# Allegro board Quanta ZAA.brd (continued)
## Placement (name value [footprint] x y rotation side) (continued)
C4736  *for15@10p/50v_4  [C0402]  169.84 81.99 0 bottom
C4737  *for15@10p/50v_4  [C0402]  172.4 82.57 180 bottom
C4748  0.1u/16v_4  [C0402]  28 67.71 0 top
C4749  0.1u/16v_4  [C0402]  19.23 70.66 180 top
C4750  0.1u/16v_4  [C0402]  21.39 68.35 0 bottom
C4751  0.1u/16v_4  [C0402]  21.52 63.9 270 top
C4752  0.1u/16v_4  [C0402]  22.54 63.9 270 top
C4753  4.7u/10v_6  [C0603]  19.36 72.54 270 top
C4754  2.2u/6.3v_6  [C0603]  20.28 63.37 270 top
C4762  typec@0.1u/25v/x5r_4  [C0402]  19.51 121.56 180 bottom
C4763  typec@0.1u/25v/x5r_4  [C0402]  19.51 120.54 180 bottom
C4764  typec@0.1u/25v_4  [C0402]  10.75 117.11 0 top
C4765  typec@10u/6.3v/x5r_6  [C0603]  28.12 109.24 90 top
C4766  typec@10u/6.3v/x5r_6  [C0603]  36.76 109.75 0 top
C4767  typec@0.1u/25v_4  [C0402]  19.49 112.54 90 top
C4768  typec@0.1u/25v_4  [C0402]  10.75 116.12 0 top
C4769  typec@10u/6.3v/x5r_6  [C0603]  36.76 108.48 0 top
C4770  typec@0.1u/25v/x5r_4  [C0402]  19.51 116.76 180 bottom
C4771  typec@0.1u/25v/x5r_4  [C0402]  19.51 117.65 180 bottom
C4772  typec@150u/6.3v_3528  [C3528]  37.65 106.06 180 top
C4773  typec@0.1u/16v_4_x7r  [C0402]  28.84 117.57 180 bottom
C4774  typec@0.1u/16v_4_x7r  [C0402]  32.01 120.62 0 bottom
C4775  *typec@10u/6.3v_6  [C0603]  27.87 114.04 0 top
C4776  typec@0.1u/16v_4_x7r  [C0402]  35.24 120.54 0 top
C4777  typec@0.1u/16v_4_x7r  [C0402]  35.24 119.53 0 top
C4778  typec@0.1u/16v_4_x7r  [C0402]  35.24 122.57 0 top
C4779  typec@0.1u/16v_4_x7r  [C0402]  35.24 121.56 0 top
C4780  typec@0.1u/16v_4_x7r  [C0402]  35.24 117.49 0 top
C4781  typec@0.1u/16v_4_x7r  [C0402]  37.27 116.48 0 top
C4782  *ioac@0.1u/16v_4  [C0402]  48.9 70.38 90 top
C4783  0.1u/16v_4  [C0402]  22.92 52.09 0 top
C4784  0.1u/16v_4_x7r  [C0402]  17.07 43.33 270 top
C4785  0.1u/16v_4_x7r  [C0402]  20.5 55.14 270 top
C4786  0.1u/16v_4_x7r  [C0402]  18.34 55.14 270 top
C4787  0.1u/16v_4_x7r  [C0402]  22.92 53.87 180 top
C4788  ev_a@10u/6.3v_6  [C0603]  223.2 121.43 90 bottom
C4793  *220p/50v_4  [C0402]  193.55 23.95 270 bottom
C4794  *220p/50v_4  [C0402]  192.59 24.07 270 bottom
C4795  *220p/50v_4  [C0402]  190.68 24.12 270 bottom
C4796  *220p/50v_4  [C0402]  191.62 24.12 270 bottom
C4797  *220p/50v_4  [C0402]  177.48 23.9 270 bottom
C4798  *220p/50v_4  [C0402]  176.51 23.9 270 bottom
C4799  *220p/50v_4  [C0402]  175.55 23.9 270 bottom
C4800  *220p/50v_4  [C0402]  174.58 23.9 270 bottom
C4801  *220p/50v_4  [C0402]  181.34 23.9 270 bottom
C4802  *220p/50v_4  [C0402]  180.37 23.9 270 bottom
C4803  *220p/50v_4  [C0402]  179.41 23.9 270 bottom
C4804  *220p/50v_4  [C0402]  178.44 23.9 270 bottom
C4805  *220p/50v_4  [C0402]  185.2 23.9 270 bottom
C4806  *220p/50v_4  [C0402]  184.23 23.9 270 bottom
C4807  *220p/50v_4  [C0402]  183.27 23.9 270 bottom
C4808  *220p/50v_4  [C0402]  182.3 23.9 270 bottom
C4809  *220p/50v_4  [C0402]  197.41 24.07 270 bottom
C4810  *220p/50v_4  [C0402]  196.45 24.07 270 bottom
C4811  *220p/50v_4  [C0402]  195.48 24.07 270 bottom
C4812  *220p/50v_4  [C0402]  194.52 24.07 270 bottom
C4813  *220p/50v_4  [C0402]  189.06 23.9 270 bottom
C4814  *220p/50v_4  [C0402]  188.09 23.9 270 bottom
C4815  *220p/50v_4  [C0402]  186.16 23.9 270 bottom
C4816  *220p/50v_4  [C0402]  187.13 23.9 270 bottom
C4817  typec@100p/50v_4  [C0402]  23.3 114.07 270 top
C4818  typec@1000p/50v_4  [C0402]  22.41 114.07 90 top
C4819  typec@100p/50v_4  [C0402]  16.44 112.54 270 top
C4820  typec@1000p/50v_4  [C0402]  15.42 112.54 90 top
C4821  1000p/50v_4  [C0402]  36.25 64.15 270 top
C4822  *fpd@1000p/50v_4  [C0402]  117.1 34.69 180 top
CN2  *aces_88511-180n  [88511-180N-18P-L]  171.38 93.36 0 top
CN4  sd-card  [SDCARD-PSDAT4-11GLBS1NN4H4-11P]  35.49 19.6 0 top
CN5  50398-04071-001  [GS12401-1011-40P-R-NH-SMT]  121.5 174.4 45 bottom
CN6  bl@kb_backlight  [50591-00401-001-4P-L]  224.2 134.09 270 bottom
CN7  crt conn  [DSUB-95-0005-01-15P]  6.62 79.15 90 bottom
CN8  fan_3p  [HS8803F-3P-L]  57.88 120.4 90 bottom
CN9  c185q2-11311-l  [SATA-C185Q2-11311-L-13P-R]  234.02 101.31 270 bottom
CN10  wlan_ngff conn(type 2230)  [NGFF-NASE0-S6701-TS48-KE-SMT]  196.3 182.75 270 bottom
CN11  rj45  [RJ45-JM361C-HP34AA03-9H-8P]  2.65 104.4 90 bottom
CN12  hdmi connector  [HDMI-10444-19001-19P]  3.35 50.5 90 bottom
CN13  usb3.0 conn  [UB3-YUSB0021-P001A-9P-SMT]  6.82 31.8 90 bottom
CN14  hdd conn  [SATA-C166FQ-12208-L-22P-R]  229.5 44.65 270 bottom
CN16  usb3.0 conn  [UB3-YUSB0021-P001A-9P-SMT]  6.82 15.2 90 bottom
CN17  tp_conn  [50503-0080N-001-8P-L]  122.5 14.95 180 bottom
CN18  spk_conn_4p  [50271-0040N-V01-4P-L]  82.6 12 270 bottom
CN20  for15@kb_conn  [196153-28021-35-28P-L]  164.92 12.65 180 bottom
CN23  ngff_ssd  [NGFF-NASM0-S6701-TS50-KM-SMT]  165.5 98.15 180 bottom
CN95  fpd@conn_aop  [196241-08021-3-8P-L]  110.5 13.45 180 bottom
CN2019  for17@kb_conn  [196153-28021-35-28P-L]  186.46 19.22 180 bottom
CN2020  db_conn  [51619-0260N-001-26P-L]  213.93 16.4 270 bottom
CN2021  typec@usb_type_c  [UB31-DX07B024XJ1AR1000-24P-SMT]  6.6 119.9 90 bottom
D1  1n4148ws  [DSM]  111.18 153.56 90 top
D2  tvs/6pf_4  [C0402]  86.77 87.45 270 bottom
D3  tvs/6pf_4  [C0402]  86.77 85.67 90 bottom
D4  *for17@tvs/6pf_4  [C0402]  133.17 75.2 0 top
D5  *for17@tvs/6pf_4  [C0402]  135.23 75.23 0 top
D6  *az5125-01j  [C0402]  13.65 53.99 90 top
D7  bat54c  [SOT323_213-2_1-1_3-2N7002W]  74.86 50.18 90 top
D8  *gs@rb500v-40  [DSM]  219.84 50.85 90 bottom
D9  1n4148ws  [DSM]  212.27 39.14 270 bottom
D10  1n4148ws  [DSM]  210.37 39.14 270 bottom
D11  *rb500v-40  [DSM]  163.38 33.34 0 bottom
D12  sdmk0340l-7-f  [DSMV]  192.87 38.95 270 bottom
D14  *rb500v-40  [DSM]  163.38 29.66 0 bottom
D15  *rb500v-40  [DSM]  196.32 44.11 270 bottom
D16  rb500v-40  [DSM]  194.62 44.11 270 bottom
D17  *rb500v-40  [DSM]  163.38 31.57 0 bottom
D18  rb500v-40  [DSM]  163.38 27.76 0 bottom
D20  *rb500v-40  [DSM]  163.38 25.85 0 bottom
D23  *vport_6  [C0603]  13.11 90.7 90 top
D24  *5.5v/25v/410p_4  [C0402]  58.62 17.05 90 top
D25  *5.5v/25v/410p_4  [C0402]  59.72 17.05 90 top
D26  *5.5v/25v/410p_4  [C0402]  54.1 17.06 90 top
D27  *5.5v/25v/410p_4  [C0402]  55.2 17.06 90 top
D28  *vport_6  [C0603]  79.18 11.68 180 top
D30  rb501v-40  [DSM]  21.27 41.29 0 top
D31  rb501v-40  [DSM]  16.44 41.25 0 top
D34  *for15@vport_6  [C0603]  151.82 19.96 270 bottom
D35  *gs@rb500v-40  [DSM]  223.02 52.05 180 bottom
D4000  gc6@bat54cw_200ma  [UMT_213-3-1_3]  229.04 113.05 270 bottom
D4001  *rb500v-40  [DSM]  160.86 35.19 0 bottom
D4002  *for17@vport_6  [C0603]  172.88 23.24 180 bottom
D4012  *rb500v-40  [DSM]  158.35 25.8 0 bottom
D4013  *for15@tvs/6pf_4  [C0402]  169.84 81.05 0 bottom
D4014  *for15@tvs/6pf_4  [C0402]  172.4 81.68 180 bottom
EC35  *120p/50v_4  [C0402]  144.33 50.29 0 top
EC36  *120p/50v_4  [C0402]  129.72 67.36 270 bottom
EC37  *0.1u/16v_4  [C0402]  124.52 67.58 270 bottom
EC38  *0.1u/16v_4  [C0402]  120.58 68.22 0 bottom
EC39  *120p/50v_4  [C0402]  117.02 67.46 0 bottom
EC40  *120p/50v_4  [C0402]  146.11 42.67 0 top
EC41  *0.1u/16v_4  [C0402]  110.55 67.71 0 bottom
EC42  *120p/50v_4  [C0402]  103.18 66.44 0 bottom
EC43  *120p/50v_4  [C0402]  91.5 67.08 270 bottom
EC44  *120p/50v_4  [C0402]  130.74 39.9 180 bottom
EC45  *120p/50v_4  [C0402]  134.42 40.41 90 bottom
EC46  *120p/50v_4  [C0402]  115.12 39.9 0 bottom
EC47  *120p/50v_4  [C0402]  111.44 39.9 180 bottom
EC48  *120p/50v_4  [C0402]  105.21 40.02 0 bottom
EC49  120p/50v_4  [C0402]  101.15 40.02 180 bottom
EC50  *0.1u/16v_4  [C0402]  98.38 41.12 0 bottom
EC51  typec@az5725-01f  [ESD-1X0_6-2P]  18.24 110.38 90 top
EC52  az5725-01f  [ESD-1X0_6-2P]  183.7 47.95 90 bottom
EC53  *az5725-01f  [ESD-1X0_6-2P]  116.05 17.87 90 bottom
EC54  *az5725-01f  [ESD-1X0_6-2P]  114.84 17.88 90 bottom
HOLE1  *hg-c354d134p2  [HG-C354D134P2]  11.6 63.9 0 top
HOLE2  *hg-c354d134p2  [HG-C354D134P2]  12.5 3.6 0 top
HOLE3  *hg-c354d134p2  [HG-C354D134P2]  217.5 3.6 0 top
HOLE4  *hg-c354d134p2  [HG-C354D134P2]  76.2 3.6 0 top
HOLE6  *hg-tc354ic236bc236d118p2  [HG-TC354IC236BC236D118P2]  231 164.4 0 top
HOLE7  *hg-tc354ic236bc236d118p2  [HG-TC354IC236BC236D118P2]  133.57 189.2 0 top
HOLE8  ev@h-c236i156d140p2  [H-C236I156D140P2]  161.11 153.04 180 bottom
HOLE9  ev@h-c236d140p2  [H-C236D140P2]  203.32 110.84 180 bottom
HOLE10  *h-tc236ic236bc256d161p2  [H-TC236IC236BC256D161P2]  94.42 94.29 180 bottom
HOLE11  *h-tc236ic236bc256d161p2  [H-TC236IC236BC256D161P2]  146.38 94.29 180 bottom
HOLE12  *h-tc236ic236bc256d161p2  [H-TC236IC236BC256D161P2]  120.4 139.29 180 bottom
HOLE13  h-c256d161p2  [H-C256D161P2]  165.5 39.9 180 bottom
HOLE14  h-c256d161p2  [H-C256D161P2]  165.5 57.9 180 bottom
HOLE15  h-c256d161p2  [H-C256D161P2]  165.5 19.9 180 bottom
HOLE16  h-tc217bc197d126p2  [H-TC217BC197D126P2]  224.55 182.75 180 bottom
HOLE17  *h-zab-2  [H-ZAB-2]  73.5 83.4 0 top
HOLE18  *h-zab-2  [H-ZAB-2]  225.5 92.4 0 top
HOLE19  *h-zab-5  [H-ZAB-5]  12 127.9 0 top
HOLE20  *h-c87d87n  [H-C87D87N]  232.75 83.4 0 top
HOLE21  *h-o146x87d146x87n  [H-O146X87D146X87N]  225.65 28.86 0 top
HOLE22  *o-zaa-1  [O-ZAA-1]  186.75 12.65 0 top
HOLE23  *hg-c315d134p2  [HG-C315D134P2]  140.58 8.05 0 top
HOLE24  *hg-c315d134p2  [HG-C315D134P2]  161.45 7.05 0 top
HOLE26  *h-c217d217n  [H-C217D217N]  216.5 182.67 0 top
J1  *jump  [JOPEN25X30_S]  89.97 27.71 90 bottom
JDIM1  ddr4-dimm1_h=5.2_std  [DDR4-D4AS0-26001-1P52-STD-SMT]  116.1 47.3 0 bottom
JDIM2  ddr4-dimm2_h=5.2_rvs  [DDR4-D4AR0-26001-1P52-RVS-SMT]  116.1 59.5 180 bottom
L4  100mhz_6  [R0603]  26.07 63.09 270 top
L5  blm18bb470_6  [R0603]  14.03 77.74 0 top
L6  blm18bb470_6  [R0603]  14.03 75.46 0 top
L7  blm18bb470_6  [R0603]  14.03 72.92 0 top
L11  blm15ag121sn1d(120,500ma)_4  [R0402]  166.48 28.11 180 bottom
L12  blm15ag121sn1d(120,500ma)_4  [R0402]  168.71 32.66 90 bottom
L13  pby160808t-600y-n(60,3a)  [R0603]  198.68 38.63 90 bottom
L16  hcb2012kf220t60/6a/22ohm_8  [R0805]  203 24.28 180 bottom
L18  hcb1608kf-121t30_3a  [R0603]  198.51 30.22 0 bottom
L19  *short_6  [S0603]  134.55 17.98 0 bottom
L22  blm15ag121sn1d(120,500ma)_4  [R0402]  187.13 45.61 270 bottom
L26  ev@hcb1005kf-330t30  [R0402]  206.66 154.96 270 bottom
L4100  ev@hcb1005kf-330t30  [R0402]  180.75 138.12 0 top
L4200  ev@hcb1005kf-330t30  [R0402]  175.2 121.56 180 top
L4201  ev@blm15px181sn1d_1.5a  [R0402]  172.4 122.71 270 top
L4206  *ev@hcb1005kf-330t30  [R0402]  180.75 137.21 0 top
L4208  100mhz_6  [R0603]  21.01 70.38 90 bottom
L4209  typec@blm18pg181sn1d_0.5a  [L0603]  29.22 112.39 180 top
LED1  led_amber/blue  [LEDLTST-S326KGJRKT-3P-SMT]  55.5 4.4 180 top
LED2  led_amber/blue  [LEDLTST-S326KGJRKT-3P-SMT]  63.5 4.39 180 top
MR1  ah9249ntr-g1  [SOT23_123-2_8-1_9]  87.5 2.5 90 top
NOREF  -  [unnamed]  194.52 190.52 0 top
NOREF#2  -  [unnamed]  16.77 10.85 0 top
NOREF#3  -  [#2]  136.76 26.79 0 top
NOREF#4  -  [#2]  181.24 -19.33 0 top
NOREF#5  -  [#2]  226.7 189.95 0 top
NOREF#6  -  [unnamed]  224.52 33.14 0 top
NOREF#7  -  [#2]  17.34 -28.92 0 top
NOREF#8  -  [#2]  88.45 33.77 180 bottom
NOREF#9  -  [#2]  26.19 13.3 180 bottom
NOREF#10  -  [unnamed]  17.74 10.61 180 bottom
NOREF#11  -  [unnamed]  142.27 187.17 180 bottom
NOREF#12  -  [unnamed]  195.74 10.59 180 bottom
PAD1  *spad-zab-1np  [SPAD-ZAB-1NP]  176.23 185.2 0 top
PAD2  *spad-zab-2np  [SPAD-ZAB-2NP]  242.4 191.62 0 top
PAD3  *spad-re157x488np  [SPAD-RE157X488NP]  203.08 74.82 0 top
PAD5  *spad-zab-3np  [SPAD-ZAB-3NP]  175.65 84.17 0 top
PAD6  *spad-c298np  [SPAD-C298NP]  140.65 84.18 0 top
PAD7  *spad-re157x491np  [SPAD-RE157X491NP]  86.17 72.79 0 top
PAD8  *spad-c298np  [SPAD-C298NP]  114.15 84.18 0 top
PAD9  *spad-c276np  [SPAD-C276NP]  44.6 41.15 0 top
PAD10  *spad-re157x1267np  [SPAD-RE157X1267NP]  86.18 24.13 0 top
PAD11  *spad-re531x205np  [SPAD-RE531X205NP]  216.32 189.9 0 top
PAD12  *spad-re157x315np  [SPAD-RE157X315NP]  194.09 64.61 0 top
PAD13  *spad-re157x1282np  [SPAD-RE157X1282NP]  194.09 24.34 0 top
PAD14  *spad-c197np  [SPAD-C197NP]  186.24 51.84 180 bottom
PAD15  *spad-zaa-1-np  [SPAD-ZAA-1-NP]  109.56 167.56 0 top
PC1  *0.01u/50v_4  [C0402]  158.73 166.75 0 top
PC2  0.1u/50v_6  [C0603]  162.52 186.02 180 top
PC3  100p/50v_4  [C0402]  153.47 186.93 270 top
PC4  *680p/50v_6  [C0603]  165.49 183.76 90 bottom
PC5  0.1u/50v_6  [C0603]  160.41 186.76 90 top
PC6  100p/50v_4  [C0402]  152.51 186.93 270 top
PC7  *100p/50v_4  [C0402]  134.83 170.99 270 top
PC8  *47p/50v_4  [C0402]  149.97 168.89 90 top
PC9  *47p/50v_4  [C0402]  152.81 168.65 90 top
PC10  1u/6.3v_4  [C0402]  138.54 167.76 180 top
PC11  *0.01u/50v_4  [C0402]  136.4 168.68 270 top
PC12  *0.01u/50v_4  [C0402]  136.43 166.92 90 top
PC13  0.1u/50v_6  [C0603]  220.35 187.14 270 bottom
PC14  0.1u/25v_4  [C0402]  140.39 167.89 90 top
PC15  470p/50v_4  [C0402]  139.05 169.23 90 top
PC16  220p/50v_4  [C0402]  137.65 169.26 90 top
PC17  gt3@0.022u/25v_4  [C0402]  144.2 170.99 90 top
PC18  gt3@0.022u/25v_4  [C0402]  143.19 170.99 90 top
PC19  2200p/50v_4  [C0402]  142.13 170.98 90 top
PC20  0.022u/25v_4  [C0402]  140.61 171.38 180 top
PC21  33p/50v_4  [C0402]  136.84 170.96 270 top
PC22  330p/50v_4  [C0402]  136.48 174.62 270 bottom
PC23  330p/50v_4  [C0402]  144.74 174.95 180 top
PC24  33p/50v_4  [C0402]  141.22 177.15 180 bottom
PC25  *0.01u/50v_4  [C0402]  149.66 177.95 0 top
PC26  1000p/50v_4  [C0402]  147.22 177.54 270 top
PC27  *0.01u/50v_4  [C0402]  144.74 179.32 0 top
PC28  560p/50v_4  [C0402]  144.71 178.05 180 top
PC29  0.01u/50v_4  [C0402]  147.4 172.41 270 top
PC30  10n/50v_4  [C0402]  145.52 181.07 90 top
PC31  0.1u/25v_4  [C0402]  146.49 181.1 270 top
PC32  0.1u/25v_4  [C0402]  136.45 177.18 180 bottom
PC33  0.1u/25v_4  [C0402]  146.77 184.75 0 top
PC34  2200p/50v_4  [C0402]  145.92 182.51 0 top
PC35  0.1u/25v_4  [C0402]  134.75 178.48 270 top
PC36  330p/50v_4  [C0402]  140.47 179.12 90 bottom
PC37  33p/50v_4  [C0402]  138.54 179.12 270 bottom
PC38  0.047u/10v_4  [C0402]  139.35 183.41 0 bottom
PC39  0.015u/50v_4  [C0402]  139.35 182.44 180 top
PC40  2200p/50v_4  [C0402]  137.8 183.13 90 bottom
PC41  *680p/50v_4  [C0402]  142.22 184.83 270 top
PC42  1000p/50v_4  [C0402]  142.42 184.8 270 bottom
PC43  0.1u/25v_4  [C0402]  138.03 185.59 0 bottom
PC44  *0.01u/50v_4  [C0402]  143.03 187.01 270 top
PC45  0.01u/50v_4  [C0402]  140.82 185.21 0 top
PC46  *0.01u/50v_4  [C0402]  144.28 184.88 270 top
PC47  10u/25v_8  [C0805]  124.63 159.14 270 top
PC48  2200p/50v_6  [C0603]  122.84 158.97 90 bottom
PC49  gt3@10u/25v_8  [C0805]  134.61 158.5 270 top
PC50  gt3@2200p/50v_6  [C0603]  132.91 158.73 90 top
PC51  2200p/50v_6  [C0603]  138.61 157.73 90 top
PC52  10u/25v_8  [C0805]  142.88 159.07 270 top
PC53  2200p/50v_6  [C0603]  158.48 158.95 90 bottom
PC54  10u/25v_8  [C0805]  156.77 159.05 270 bottom
PC55  1000p/50v_4  [C0402]  120.33 156.23 270 top
PC56  gt3@1000p/50v_4  [C0402]  128.07 155.77 270 top
PC57  1000p/50v_4  [C0402]  150.6 154.58 0 top
PC58  1000p/50v_4  [C0402]  141.57 155.07 180 top
PC59  330u/2v_7343  [CC7343]  135.57 141.88 180 bottom
PC61  *0.1u/50v_6  [C0603]  49.14 44.89 270 top
PC65  10u/6.3v_6  [C0603]  48.18 51.11 180 top
PC70  *1u/16v_6  [C0603]  48.2 52.52 0 top
PC71  10u/6.3v_6  [C0603]  36.05 47.19 90 top
PC74  0.1u/50v_6  [C0603]  48.15 49.77 0 top
PC75  *0.1u/16v_4  [C0402]  163.99 62.96 0 bottom
PC76  10u/6.3v_6  [C0603]  159.19 62.25 0 bottom
PC77  *1u/16v_6  [C0603]  156.65 61.11 270 bottom
PC78  0.1u/50v_6  [C0603]  159.19 60.85 180 bottom
PC79  1u/6.3v_4  [C0402]  156.77 62.76 0 bottom
PC80  10u/6.3v_6  [C0603]  156.8 73.38 270 bottom
PC81  1u/6.3v_4  [C0402]  49.04 53.66 0 top
PC83  1u/25v_4  [C0402]  64.06 18.38 0 bottom
PC84  *0.1u/16v_4  [C0402]  66.73 21.58 180 bottom
PC85  0.1u/16v_4  [C0402]  62.67 23.82 270 bottom
PC86  ev@10u/25v_8  [C0805]  213.8 71.27 180 bottom
PC87  *0.1u/16v_4  [C0402]  64.7 20.09 0 top
PC88  0.1u/16v_4  [C0402]  64.7 21.1 0 top
PC89  0.047u/10v_4  [C0402]  67.82 72.61 90 bottom
PC90  1u/25v_4  [C0402]  64.01 23.44 0 bottom
PC91  0.1u/16v_4  [C0402]  62.64 17.98 90 bottom
PC92  ev@0.047u/10v_4  [C0402]  216.53 175.96 0 bottom
PC97  10u/6.3v_6  [C0603]  61.37 24.28 270 bottom
PC98  1000p/50v_4  [C0402]  60.79 20.34 0 bottom
PC99  gt3@10u/25v_8  [C0805]  51.06 80.46 270 top
PC100  gt3@2200p/50v_4  [C0402]  55.43 80.16 270 bottom
PC101  *2.2n/50v_4  [C0402]  69.3 100.73 180 top
PC102  0.1u/50v_6  [C0603]  48.67 109 270 top
PC103  2200p/50v_4  [C0402]  47.55 35.45 90 top
PC104  0.1u/50v_6  [C0603]  50.78 116.61 0 top
PC105  10u/6.3v_6  [C0603]  61.32 17.39 90 bottom
PC106  1u/25v_4  [C0402]  59.39 52.09 0 bottom
PC107  *0.1u/16v_4  [C0402]  61.86 55.57 180 bottom
PC108  0.1u/16v_4  [C0402]  57.84 56.74 180 bottom
PC109  *ev@1u/10v_4  [C0402]  52.15 70.25 180 top
PC110  *ev@22p/50v_4  [C0402]  194.42 56.76 0 bottom
PC111  0.1u/16v_4  [C0402]  61.8 54.55 180 bottom
PC112  *0.1u/16v_4  [C0402]  61.88 53.49 180 bottom
PC113  *ev@2.2n/50v_4  [C0402]  52.38 72.16 180 top
PC114  0.1u/16v_4  [C0402]  57.66 52.09 180 bottom
PC115  0.1u/50v_6  [C0603]  162.52 187.47 0 top
PC116  0.47u/25v_6  [C0603]  161.27 184.6 0 top
PC117  2200p/50v_6  [C0603]  166.11 180.49 0 bottom
PC118  10u/25v_8  [C0805]  166.01 180.06 180 top
PC119  47n/50v_6  [C0603]  161.77 183.2 180 top
PC120  10u/25v_8  [C0805]  164.27 171.7 90 bottom
PC121  2200p/50v_6  [C0603]  165.92 171.67 270 bottom
PC122  2.2u/10v_6  [C0603]  160.64 178.84 90 top
PC123  0.01u/50v_4  [C0402]  159.24 178.68 90 top
PC124  2200p/50v_6  [C0603]  229.22 185.64 270 top
PC125  *100p/50v_4  [C0402]  160.48 174.92 90 top
PC126  0.1u/50v_6  [C0603]  158.02 172.77 0 top
PC127  10u/25v_8  [C0805]  162.34 171.7 90 bottom
PC128  0.1u/50v_6  [C0603]  230.69 185.67 270 top
PC129  3300p/50v_4  [C0402]  135.49 170.56 0 bottom
PC130  0.1u/25v_4  [C0402]  159.09 174.67 90 top
PC131  0.1u/25v_4  [C0402]  157.21 173.88 180 top
PC132  0.1u/25v_4  [C0402]  155.81 173.68 270 top
PC133  1n/50v_4  [C0402]  210.17 191.08 90 bottom
PC134  sp@0.1u/25v_4  [C0402]  140.66 172.86 180 bottom
PC135  2200p/50v_4  [C0402]  146.18 175.36 90 top
PC136  47n/50v_6  [C0603]  211.54 190.67 270 bottom
PC137  1u/25v_4  [C0402]  59.57 56.76 0 bottom
PC138  33u/25v_6x4.5  [ECAP6_3X6_1-7_2]  130.71 168.83 0 bottom
PC139  2200p/50v_4  [C0402]  143.29 184.86 270 top
PC140  2200p/50v_6  [C0603]  212.58 178.96 270 bottom
PC141  0.1u/50v_6  [C0603]  211.08 178.96 90 bottom
PC142  0.1u/50v_6  [C0603]  122.79 163.82 90 bottom
PC143  gt3@0.1u/50v_6  [C0603]  130.99 163.67 90 bottom
PC144  0.1u/50v_6  [C0603]  142.37 163.47 90 bottom
PC145  0.1u/50v_6  [C0603]  153.47 163.52 90 bottom
PC146  4.7u/10v_6  [C0603]  117.79 162.83 90 bottom
PC147  gt3@4.7u/10v_6  [C0603]  126.47 159.94 270 bottom
PC148  10u/25v_8  [C0805]  124.67 159.13 270 bottom
PC149  4.7u/10v_6  [C0603]  136.48 159.68 270 bottom
PC150  0.1u/50v_6  [C0603]  122.84 158.97 90 top
PC151  4.7u/10v_6  [C0603]  148.39 159.63 270 bottom
PC152  gt3@10u/25v_8  [C0805]  134.61 158.5 270 bottom
PC153  gt3@0.1u/50v_6  [C0603]  132.89 158.73 90 bottom
PC154  0.1u/50v_6  [C0603]  142.65 158.77 90 bottom
PC155  10u/25v_8  [C0805]  144.39 159.06 270 bottom
PC156  0.1u/50v_6  [C0603]  159.89 158.94 90 bottom
PC157  10u/25v_8  [C0805]  154.81 159.04 270 bottom
PC158  gt3@330u/2v_7343  [CC7343]  111.02 143.01 180 bottom
PC159  0.1u/16v_4  [C0402]  134.37 145.18 90 bottom
PC160  gt3@0.1u/16v_4  [C0402]  133.41 145.18 90 bottom
PC161  0.1u/16v_4  [C0402]  132.9 138.2 270 bottom
PC162  330u/2v_7343  [CC7343]  144.61 149.88 90 bottom
PC163  330u/2v_7343  [CC7343]  110.94 138.21 180 bottom
PC164  22u/6.3v_8  [C0805]  125.66 137.94 270 bottom
PC165  22u/6.3v_8  [C0805]  156.33 146.84 180 bottom
PC166  gt3@22u/6.3v_8  [C0805]  129.47 142.01 90 bottom
PC167  gt3@22u/6.3v_8  [C0805]  80.14 123.77 0 bottom
PC168  22u/6.3v_8  [C0805]  127.56 137.94 270 bottom
PC169  22u/6.3v_8  [C0805]  156.33 144.84 180 bottom
PC170  22u/6.3v_8  [C0805]  125.41 142.01 90 bottom
PC171  0.1u/16v_4  [C0402]  150.27 142.08 90 bottom
PC172  22u/6.3v_8  [C0805]  127.44 142.01 90 bottom
PC173  10u/6.3v_6  [C0603]  56.27 57.73 270 bottom
PC174  10u/6.3v_6  [C0603]  55.96 51.25 90 bottom
PC175  1000p/50v_4  [C0402]  60.79 21.33 0 bottom
PC176  1000p/50v_4  [C0402]  55.81 53.87 0 bottom
PC177  1000p/50v_4  [C0402]  55.81 54.88 0 bottom
PC178  *ev@0.01u/50v_4  [C0402]  203.1 55.98 270 bottom
PC179  ev@0.1u/50v_6  [C0603]  176.61 72.64 180 bottom
PC180  typec@0.1u/16v_4  [C0402]  39.07 93.7 90 top
PC181  10u/25v_8  [C0805]  53.49 62.03 90 top
PC182  ev@0.22u/25v_6  [C0603]  196.91 63.75 180 bottom
PC183  ev@1000p/50v_6  [C0603]  191.57 71.62 180 top
PC184  ev@2200p/50v_4  [C0402]  213.34 68.14 180 bottom
PC185  typec@1u/25v_4  [C0402]  35.49 95.83 0 top
PC186  ev@330u/2v_7343  [CC7343]  208.36 90.22 0 bottom
PC187  *ev@1u/10v_4  [C0402]  212.58 58.64 90 bottom
PC188  ev@1000p/50v_6  [C0603]  197.87 74.42 0 top
PC189  typec@0.1u/16v_4  [C0402]  34.22 98.17 90 top
PC190  ev@10u/6.3v_8  [C0805]  185.35 92.86 0 top
PC191  ev@0.1u/16v_4  [C0402]  207.68 96.21 180 bottom
PC192  ev@10u/6.3v_8  [C0805]  207.57 94.48 180 bottom
PC193  ev@0.1u/16v_4  [C0402]  205.85 102 180 top
PC194  22u/6.3v_8  [C0805]  66.96 67.19 0 top
PC195  ev@1u/10v_4  [C0402]  199.17 64.43 270 bottom
PC196  *0.1u/16v_4  [C0402]  42.4 53.22 90 top
PC197  *680p/50v_6  [C0603]  59.05 59.58 0 top
PC198  *10u/6.3v_6  [C0603]  43.22 60.46 270 top
PC199  ev@4700p/25v_4  [C0402]  195.23 60.5 0 bottom
PC200  ev@2700p/50v_4  [C0402]  205.59 57.2 90 bottom
PC201  ev@330u/2v_7343  [CC7343]  185.48 96.03 180 bottom
PC202  0.1u/50v_6  [C0603]  47.98 60.1 90 top
PC203  *0.1u/16v_4  [C0402]  43.37 53.22 90 top
PC204  ev@330u/2.5v_6x4.2  [ECAP6_3X6_1-7_2]  185.65 101.98 0 bottom
PC205  22u/6.3v_8  [C0805]  68.76 58.37 90 top
PC206  ev@1u/10v_4  [C0402]  200.97 55.98 270 bottom
PC207  10u/6.3v_6  [C0603]  41.78 59.29 270 top
PC208  typec@10u/6.3v_6  [C0603]  35.41 97.71 90 top
PC209  ev@2200p/50v_4  [C0402]  176.61 73.78 0 bottom
PC210  typec@1000p/50v_4  [C0402]  38.23 99.54 270 top
PC211  ev@10u/25v_8  [C0805]  176.54 70.53 0 bottom
PC212  0.1u/16v_4  [C0402]  40.2 57.53 0 top
PC213  10u/25v_8  [C0805]  55.9 63.97 90 bottom
PC214  *typec@0.1u/16v_4  [C0402]  37.9 93.67 90 top
PC215  0.1u/16v_4  [C0402]  67.57 68.69 0 bottom
PC216  22u/6.3v_8  [C0805]  66.96 67.19 0 bottom
PC217  1u/6.3v_4  [C0402]  49.47 57.01 270 top
PC218  0.033u/10v_4  [C0402]  39.6 55.61 0 top
PC219  22u/6.3v_8  [C0805]  68.13 57.55 90 bottom
PC220  ev@10u/25v_8  [C0805]  176.54 68.6 0 bottom
PC221  ev@22p/50v_4  [C0402]  195.23 59.51 0 bottom
PC222  gt3@22uf/6.3v_6  [C0603]  52.21 94.7 0 bottom
PC223  gt3@22uf/6.3v_6  [C0603]  52.84 92.68 0 top
PC224  *ev@33u/25v_6x4.5  [ECAP6_3X6_1-7_2]  217.07 84.53 270 bottom
PC225  gt3@22uf/6.3v_6  [C0603]  52.26 96.22 0 bottom
PC226  gt3@0.1u/16v_4  [C0402]  58.6 95.65 180 bottom
PC227  *ev@0.01u/50v_4  [C0402]  196.53 54.15 90 bottom
PC228  gt3@10u/25v_8  [C0805]  49.03 78.58 270 top
PC229  gt3@0.1u/25v_4  [C0402]  55.81 78.86 180 bottom
PC230  gt3@1u/10v_4  [C0402]  57.16 82.9 270 bottom
PC231  gt3@0.1u/50v_6  [C0603]  58.5 85.16 270 bottom
PC232  *10u/6.3v_6  [C0603]  161.35 50.11 270 bottom
PC233  10u/6.3v_6  [C0603]  162.72 44.9 180 bottom
PC234  22u/6.3v_6  [C0603]  61.72 93.08 270 bottom
PC235  *1000p/50v_4  [C0402]  63.57 70.86 90 top
PC236  *22u/6.3v_6  [C0603]  63.83 93.29 0 bottom
PC237  2200p/50v_6  [C0603]  62.06 76.98 90 top
PC238  10u/25v_8  [C0805]  59.61 73.77 90 bottom
PC239  22u/6.3v_6  [C0603]  60.34 93.08 270 bottom
PC240  0.47uf/4v_4  [C0402]  168.79 45.61 180 bottom
PC241  0.1u/16v_4  [C0402]  162.57 50.13 90 bottom
PC242  22u/6.3v_6  [C0603]  63.8 96.12 0 bottom
PC243  10u/6.3v_6  [C0603]  69.75 74.02 180 bottom
PC244  4.7u/6.3v_6  [C0603]  164.6 49.91 0 bottom
PC245  22u/6.3v_6  [C0603]  61.78 93.09 270 top
PC246  ev@0.01u/50v_4  [C0402]  209.91 175.94 90 top
PC247  *ev@68p/50v_4  [C0402]  204.68 177.54 180 bottom
PC248  22u/6.3v_6  [C0603]  63.78 94.73 0 bottom
PC249  ev@10u/6.3v_6  [C0603]  209.91 175.94 90 bottom
PC250  0.1u/16v_4  [C0402]  63.05 93.03 270 top
PC251  ev@0.1u/50v_6  [C0603]  213.47 69.49 0 bottom
PC252  ev@1u/6.3v_4  [C0402]  204.68 178.53 180 bottom
PC253  ev@0.22u/25v_6  [C0603]  202.8 63.7 0 bottom
PC254  ev@10u/25v_8  [C0805]  213.8 73.55 180 bottom
PC267  0.1u/25v_6  [C0603]  67.81 78.05 0 bottom
PC268  *22u/6.3v_6  [C0603]  60.34 93.09 270 top
PC269  *0.1u/25v_4  [C0402]  60.74 77.13 270 top
PC270  *680p/50v_6  [C0603]  62.92 80.92 90 top
PC271  *0.01u/25v_4  [C0402]  61.15 71.25 0 bottom
PC272  *0.047u/10v_4  [C0402]  65.83 70.88 90 bottom
PC273  ev@22u/6.3v_6  [C0603]  220.9 160.11 180 bottom
PC274  *ev@1000p/50v_4  [C0402]  222.01 178.67 180 bottom
PC275  *ev@22u/6.3v_6  [C0603]  220.96 155.89 180 bottom
PC276  ev@2200p/50v_6  [C0603]  223.7 171.29 270 top
PC277  ev@10u/25v_8  [C0805]  223.94 175.55 270 bottom
PC278  ev@22u/6.3v_6  [C0603]  220.95 158.66 180 bottom
PC279  ev@22u/6.3v_6  [C0603]  220.94 157.26 180 bottom
PC280  ev@10u/6.3v_6  [C0603]  215.5 174.81 0 bottom
PC281  ev@22u/6.3v_6  [C0603]  223.3 162.91 180 bottom
PC282  ev@22u/6.3v_6  [C0603]  223.31 164.3 180 bottom
PC283  0.1u/25v_4  [C0402]  53.4 68.47 0 top
PC284  *330u/2.5v_6x4.2  [ECAP6_3X6_1-7_2]  72.33 69.64 270 bottom
PC285  0.1u/25v_4  [C0402]  56.75 63.59 270 top
PC286  2200p/50v_4  [C0402]  57.32 63.71 270 bottom
PC287  ev@0.1u/16v_4  [C0402]  220.92 159.35 180 top
PC288  *ev@22u/6.3v_6  [C0603]  223.32 161.56 180 bottom
PC289  ev@0.1u/25v_6  [C0603]  215.51 171.91 180 bottom
PC290  *ev@680p/50v_6  [C0603]  221.09 172.66 90 top
PC291  *ev@0.1u/25v_4  [C0402]  224.97 171.29 90 top
PC292  *ev@0.01u/25v_4  [C0402]  223.76 177.72 180 bottom
PC293  *ev@0.047u/10v_4  [C0402]  218.56 178.07 270 bottom
PC300  *ev@0.1u/16v_4  [C0402]  204.6 173.27 180 bottom
PC301  *ev@22p/50v_4  [C0402]  204.65 174.52 0 bottom
PC302  ev@22u/6.3v_6  [C0603]  213.72 160.45 90 bottom
PC303  ev@0.1u/16v_4  [C0402]  212.48 160.45 270 bottom
PC304  *ev@2200p/50v_4  [C0402]  211.21 173.76 90 bottom
PC328  ev@330u/2.5v_6x4.2  [ECAP6_3X6_1-7_2]  208.59 100.73 180 bottom
PC6098  4.7u/6.3v_6  [C0603]  56.34 39.54 180 bottom
PC6100  0.1u/25v_4  [C0402]  48.8 39.33 180 top
PC6212  33u/25v_6x4.5  [ECAP6_3X6_1-7_2]  216.97 99.97 270 bottom
PC6213  0.1u/50v_6  [C0603]  51.57 43.58 0 top
PC6214  2200p/50v_4  [C0402]  58.35 46.3 270 bottom
PC6215  0.1u/50v_6  [C0603]  51.24 33.78 180 top
PC6216  10u/25v_8  [C0805]  56.88 46.58 270 bottom
PC6218  2200p/50v_4  [C0402]  57.51 30.2 90 top
PC6219  10u/6.3v_6  [C0603]  48.42 38.02 180 top
PC6220  10u/25v_8  [C0805]  56.01 30.4 90 bottom
PC6221  *680p/50v_6  [C0603]  62.77 26.46 0 bottom
PC6222  *680p/50v_6  [C0603]  60.79 49.07 0 top
PC6224  220u/6.3v_6x4.2  [ECAP6_3X6_1-7_2]  72.65 55.01 270 bottom
PC6225  0.1u/50v_6  [C0603]  74.48 48.91 0 bottom
PC6226  0.1u/50v_6  [C0603]  67.42 37.52 180 bottom
PC6227  220u/6.3v_6x4.2  [ECAP6_3X6_1-7_2]  72.68 39.44 270 bottom
PC6228  1000p/50v_4  [C0402]  131.17 173.43 90 top
PC6229  33u/25v_6x4.5  [ECAP6_3X6_1-7_2]  228.89 175.18 270 bottom
PC6230  22u/6.3v_6  [C0603]  78.59 98.34 270 bottom
PC6231  *22u/6.3v_6  [C0603]  79.94 97.17 90 bottom
PC6232  10u/25v_8  [C0805]  55.94 30.12 90 top
PC6233  10u/25v_8  [C0805]  53.52 28.34 90 top
PD1  pdz5.6b  [DSM]  151.39 169.37 270 top
PD2  pdz5.6b  [DSM]  154.19 169.35 270 top
PD3  p4smafj20a  [D-DO-214AC]  230.08 183.48 270 bottom
PD4  da2j10100l  [DSM]  42.3 109.09 0 top
PD8  sv1040  [D-TO277_213-6_1X4_3]  224.24 189.12 0 bottom
PJ1  50458-00801-v01  [50458-00801-V02-8P-L]  153.55 178.38 0 bottom
PJ3  power conn  [50320-0040N-001-4P-L-SMT]  238.43 191.12 290 bottom
PL1  6.8uh_7x7x3  [CHOKE-PCMC063T-3R3MN-SMT]  172.83 179.83 90 bottom
PL2  0.15uh_7x7x4  [CHOKE-PCMC063T-R82MN-4P-SMT]  119.64 151.2 270 bottom
PL3  gt3@0.15uh_7x7x4  [CHOKE-PCMC063T-R82MN-4P-SMT]  128.73 151.12 270 bottom
PL4  0.15uh_7x7x4  [CHOKE-PCMC063T-R82MN-4P-SMT]  138.59 150.36 270 bottom
PL5  0.47uh_7x7x3  [CHOKE-PCMC063T-R82MN-4P-SMT]  150.76 148.46 270 bottom
PL9  ev@0.36uh_10x10x4  [CHOKE-ETQP4LR36WFC-SMT]  197.92 86.89 90 bottom
PL10  ev@0.36uh_10x10x4  [CHOKE-ETQP4LR36WFC-SMT]  186.52 86.86 90 bottom
PL11  1uh_7x7x3  [CHOKE-PCMC063T-3R3MN-SMT]  66.97 62.65 0 bottom
PL13  gt3@0.68uh_7x7x3  [CHOKE-PCMC063T-3R3MN-SMT]  55.84 90.24 90 bottom
PL14  ev@1uh_7x7x3  [CHOKE-PCMC063T-3R3MN-SMT]  211.36 166.21 270 bottom
PL15  0.68uh_7x7x3  [CHOKE-PCMC063T-3R3MN-SMT]  62.83 85.66 90 bottom
PL17  2.2uh/1.85a_2.5x2x1.2  [L3_2X2_5-1_55]  164.06 47.01 180 bottom
PL18  ev@0.68uh_7x7x3  [CHOKE-PCMC063T-3R3MN-SMT]  218.39 165.23 270 bottom
PL6012  2.2uh_7x7x3  [CHOKE-PCMC063T-3R3MN-SMT]  67.93 47.21 0 bottom
PL6013  2.2uh_7x7x3  [CHOKE-PCMC063T-3R3MN-SMT]  67.39 32.35 180 bottom
PQ1  aon6414al  [SO-8FL-5P-OA]  152.46 168.7 0 bottom
PQ3  2n7002k  [SOT23_213-3_3-2]  47.55 32.53 270 top
PQ4  *2n7002k  [SOT23_213-3_3-2]  38.11 41.09 270 top
PQ5  2n7002k  [SOT23_213-3_3-2]  70.77 94.08 180 top
PQ6  dtc144eu  [UMT_213-3-1_3]  72.93 106.93 0 top
PQ7  2n7002k  [SOT23_213-3_3-2]  73.97 103.4 180 top
PQ8  2n7002k  [SOT23_213-3_3-2]  70.11 103.14 90 top
PQ9  2n7002k  [SOT23_213-3_3-2]  41.97 116.1 270 top
PQ10  *2n7002k  [SOT23_213-3_3-2]  38.92 32.53 270 top
PQ11  dtc144eu  [UMT_213-3-1_3]  42.47 33.67 270 top
PQ12  ao3409  [SOT23_213-3_3-2]  44.64 113.27 270 top
PQ13  dtc144eu  [UMT_213-3-1_3]  41.08 112.31 90 top
PQ14  2n7002k  [SOT23_213-3_3-2]  46.16 108.22 90 top
PQ15  ev@pdtc143tt  [SOT23_213-3_3-2]  56.95 70.5 270 top
PQ16  ev@2n7002k  [SOT23_213-3_3-2]  49.71 73.43 270 top
PQ17  ev@2n7002k  [SOT23_213-3_3-2]  158.55 40.66 90 bottom
PQ18  *ev@2n7002k  [SOT23_213-3_3-2]  210.06 58.36 0 bottom
PQ19  ev@ao3404  [SOT23_213-3_3-2]  198.81 106.7 180 bottom
PQ20  aon7410  [WDFN5-3_05X3_05-65]  165.72 183.23 0 top
PQ21  aon7410  [WDFN5-3_05X3_05-65]  170.21 180.33 180 top
PQ22  aon6414al  [SO-8FL-5P-OA]  216.82 189.53 180 bottom
PQ23  ao3404  [SOT23_213-3_3-2]  76.13 99.46 90 bottom
PQ24  aon7410  [WDFN5-3_05X3_05-65]  59.86 66.15 270 bottom
PQ25  aon7752  [WDFN5-3_05X3_05-65]  59.73 60.42 180 bottom
PQ26  mdv1528q  [WDFN5-3_05X3_05-65]  75.98 93.42 0 bottom
PQ27  ev@aon6752  [SO-8FL-5P-OA]  200.97 76.35 180 bottom
PQ30  ev@aon6414al  [SO-8FL-5P-OA]  180.73 71.37 0 bottom
PQ33  ev@aon6414al  [SO-8FL-5P-OA]  209.53 77.24 180 bottom
PQ34  ev@aon6752  [SO-8FL-5P-OA]  188.55 71.42 0 bottom
PQ40  *ev@2n7002k  [SOT23_213-3_3-2]  151.57 174.9 90 top
PQ41  ev@aon6414al  [SO-8FL-5P-OA]  209.53 70.53 180 bottom
PQ42  ev@aon6752  [SO-8FL-5P-OA]  201.02 70.17 180 bottom
PQ43  ev@aon6414al  [SO-8FL-5P-OA]  181.09 77.62 0 bottom
PQ44  ev@aon6752  [SO-8FL-5P-OA]  188.55 77.59 0 bottom
PQ6053  aon7752  [WDFN5-3_05X3_05-65]  61.02 48.36 180 bottom
PQ6054  aon7410  [WDFN5-3_05X3_05-65]  61.19 43.58 0 bottom
PQ6056  aon6978  [POWER-5X6-1_27-7P]  60.03 30.75 90 bottom
PQ6057  *2n7002k  [SOT23_213-3_3-2]  37.65 53.11 270 top
PQ6058  *2n7002k  [SOT23_213-3_3-2]  33.84 53.11 270 top
PQ6065  *ao3404  [SOT23_213-3_3-2]  158.83 51.66 90 bottom
PQ6066  *2n7002k  [SOT23_213-3_3-2]  157.79 57.93 180 bottom
PR1  100k/f_4  [R0402]  161.55 180.61 180 top
PR2  *4.7_6  [R0603]  167.77 183.18 0 bottom
PR3  137k/f_4  [R0402]  155.3 185.47 180 top
PR4  100k/f_4  [R0402]  165.23 181.93 180 bottom
PR5  20_1206  [R1206]  194.49 181.35 180 top
PR6  100_4  [R0402]  149.97 170.62 90 top
PR7  100_4  [R0402]  152.79 170.59 90 top
PR8  100_4  [R0402]  155.96 170.28 90 top
PR9  1m_4  [R0402]  154.54 173.68 270 top
PR10  *0_4  [R0402]  157.49 170.83 0 top
PR11  100k_4  [R0402]  151.45 181.33 180 top
PR12  *short_4  [S0402]  152.58 178.61 270 top
PR13  *0_4  [R0402]  153.6 178.61 270 top
PR14  316k/f_4  [R0402]  159.44 176.58 90 top
PR15  100k/f_4  [R0402]  160.38 176.6 270 top
PR16  10k_4  [R0402]  154.06 176.63 90 top
PR17  10/f_6  [R0603]  138.41 169.29 0 bottom
PR18  gt3@100k/f_4  [R0402]  142.78 172.89 180 bottom
PR19  gt3@100k/f_6  [R0603]  141.08 166.64 0 bottom
PR20  3.65k/f_6  [R0603]  138.28 167.48 0 bottom
PR21  1k/f_4  [R0402]  141.74 168.8 180 top
PR22  11k/f_4  [R0402]  140.6 170.38 0 top
PR23  2k/f_4  [R0402]  139.02 170.99 90 top
PR24  1k/f_4  [R0402]  137.8 170.96 90 top
PR25  *short_4  [S0402]  136.51 173.37 90 top
PR26  *short_4  [S0402]  144.71 172.66 0 bottom
PR27  *short_4  [S0402]  144.71 172.66 0 top
PR28  *short_4  [S0402]  133.53 171.85 180 top
PR29  *short_4  [S0402]  144.74 173.96 0 top
PR30  *short_4  [S0402]  133.53 172.87 180 top
PR31  *10_4  [R0402]  148.32 177.54 90 top
PR32  *short_4  [S0402]  133.53 173.76 180 top
PR33  *short_4  [S0402]  149.23 175.64 90 top
PR34  499/f_4  [R0402]  147.66 176.16 180 top
PR35  49.9/f_4  [R0402]  133.53 174.64 180 top
PR36  2k/f_4  [R0402]  144.74 176.96 180 top
PR37  *short_4  [S0402]  47.46 46.64 0 top
PR38  *short_4  [S0402]  147.78 173.88 180 top
PR39  *10_4  [R0402]  148.44 172.41 90 top
PR40  10_4  [R0402]  133.52 175.57 0 top
PR41  1k/f_4  [R0402]  147.4 183.03 270 top
PR42  *short_4  [S0402]  142.04 180.36 180 bottom
PR43  *short_4  [S0402]  142.04 181.38 180 bottom
PR44  *2k/f_4  [R0402]  141.36 182.82 270 top
PR45  301/f_4  [R0402]  142.42 182.82 270 bottom
PR46  *short_4  [S0402]  137.47 181.1 270 top
PR47  *short_4  [S0402]  136.51 181.1 270 top
PR48  1k/f_4  [R0402]  138.03 184.53 180 bottom
PR49  *10_4  [R0402]  142.09 187.01 90 top
PR50  *short_4  [S0402]  144.76 186.41 180 top
PR51  *10_4  [R0402]  145.27 184.88 90 top
PR52  *short_4  [S0402]  144.76 187.47 180 top
PR53  100k_4  [R0402]  43.87 45.23 0 top
PR54  100k_4  [R0402]  47.92 45.3 90 top
PR55  *short_6  [S0603]  136.48 161.08 270 top
PR56  *short_6  [S0603]  148.39 162.22 270 bottom
PR57  2.2/f_6  [R0603]  121.04 154.55 0 top
PR58  gt3@2.2/f_6  [R0603]  128.76 154.15 0 top
PR59  2.2/f_6  [R0603]  151.01 152.88 270 top
PR60  2.2/f_6  [R0603]  141.16 153.37 270 top
PR61  *short_6  [S0603]  120.25 162.86 180 top
PR62  *short_6  [S0603]  126.52 161.13 270 top
PR68  *short_4  [S0402]  45.09 51.42 0 top
PR69  *short_4  [S0402]  162.44 62.1 270 bottom
PR73  100k_4  [R0402]  163 64.23 180 bottom
PR75  100k_4  [R0402]  160.99 62.1 90 bottom
PR81  *short_4  [S0402]  159.57 59.33 180 bottom
PR82  *short_4  [S0402]  64.58 74.86 90 top
PR83  *short_4  [S0402]  65.82 70.87 90 top
PR84  *ev@100_4  [R0402]  180.78 83.13 90 bottom
PR85  *ev@100_4  [R0402]  177.91 83.13 90 bottom
PR86  5.1k/f_4  [R0402]  62.56 70.86 270 top
PR87  *short_4  [S0402]  64.79 70.86 90 bottom
PR88  10_6  [R0603]  67.61 72.73 270 top
PR89  ev@2.2/f_6  [R0603]  198.61 76.52 90 top
PR90  *4.7_6  [R0603]  61.76 59.56 0 top
PR91  ev@2.2/f_6  [R0603]  188.88 71.6 180 top
PR92  20k/f_4  [R0402]  63.57 70.86 90 bottom
PR93  *0_4  [R0402]  64.78 70.88 90 top
PR94  *short_4  [S0402]  66.84 70.86 90 bottom
PR95  ev@2.2/f_6  [R0603]  196.09 62.33 180 bottom
PR96  ev@2.2/f_6  [R0603]  203.54 62.28 0 bottom
PR97  73.2k/f_4  [R0402]  62.58 70.86 270 bottom
PR98  *4.7_6  [R0603]  62.92 83.59 90 top
PR99  2.2_6  [R0603]  68.98 76.07 270 bottom
PR100  ev@20k/f_4  [R0402]  220.46 178.1 90 bottom
PR101  *ev@10k_4  [R0402]  206.08 60.68 0 bottom
PR102  *ev@0_4  [R0402]  206.05 58.67 180 bottom
PR103  *ev@0_4  [R0402]  218.75 176.16 0 top
PR104  *ev@10k_4  [R0402]  206.08 59.68 0 bottom
PR105  *ev@5.1k/f_4  [R0402]  206.64 57.2 90 bottom
PR106  ev@20k/f_4  [R0402]  204.17 57.55 180 bottom
PR107  100k/f_4  [R0402]  41.57 51.88 0 top
PR108  ev@14k/f_4  [R0402]  220.57 179.72 0 bottom
PR109  *short_4  [S0402]  219.43 178.07 270 bottom
PR110  *short_4  [S0402]  217.19 177.74 270 bottom
PR111  ev@10_6  [R0603]  217.07 176.15 90 top
PR112  *short_4  [S0402]  205.44 55.57 0 bottom
PR113  ev@20k/f_4  [R0402]  200.01 55.98 90 bottom
PR114  ev@18k/f_4  [R0402]  204.1 55.98 90 bottom
PR115  ev@2k/f_4  [R0402]  202.14 55.98 270 bottom
PR116  ev@73.2k/f_4  [R0402]  222.01 177.71 0 bottom
PR117  *short_4  [S0402]  217.86 173.5 270 top
PR118  ev@16k/f_6  [R0603]  193.5 59.84 90 bottom
PR119  34k/f_4  [R0402]  37.42 46.76 90 top
PR120  *ev@4.7_6  [R0603]  219.13 172.74 270 top
PR121  30k/f_4  [R0402]  37.47 48.59 90 top
PR122  *short_4  [S0402]  218.56 178.07 270 top
PR123  ev@2.2_6  [R0603]  215.51 173.42 0 bottom
PR133  34k/f_4  [R0402]  160.53 72.03 180 bottom
PR135  *gt3@100k/f_4  [R0402]  50.32 83.56 180 bottom
PR136  *short_4  [S0402]  50.32 83.15 180 top
PR137  *22_8  [R0805]  39.51 44.02 0 top
PR138  22_8  [R0805]  75.48 94.23 0 top
PR139  22_8  [R0805]  76.43 105.66 0 top
PR140  1m_6  [R0603]  69.6 107.56 180 top
PR141  1m_6  [R0603]  69.58 106.01 180 top
PR142  1m_6  [R0603]  67.49 102.92 90 top
PR143  *short_6  [S0603]  200.41 64.84 90 bottom
PR144  200k/f_4  [R0402]  51.85 106.44 270 top
PR145  200k/f_4  [R0402]  53.07 106.44 270 top
PR146  1.47k/f_4  [R0402]  50.76 106.41 270 top
PR147  *100k/f_6  [R0603]  42.47 31.26 180 top
PR148  1m_6  [R0603]  46.28 35.71 90 top
PR150  1m_6  [R0603]  44.76 32.66 90 top
PR151  1m_6  [R0603]  44.76 35.71 90 top
PR152  1m_6  [R0603]  44.51 110.76 0 top
PR153  *220_8  [R0805]  38.92 36.09 90 top
PR154  *short_6  [S0603]  48.02 115.36 180 top
PR155  200k_6  [R0603]  48.7 112.9 90 top
PR156  43.2k/f_4  [R0402]  161.02 73.4 90 bottom
PR157  ev@1m_6  [R0603]  58.6 73.04 180 top
PR158  ev@100k_4  [R0402]  52.15 69.39 0 top
PR159  ev@1m_6  [R0603]  55.81 73.04 180 top
PR160  *short_4  [S0402]  54.01 70.48 90 top
PR161  ev@1m_6  [R0603]  52.38 73.93 90 top
PR162  *short_4  [S0402]  178.87 83.13 90 bottom
PR163  *short_4  [S0402]  179.84 83.13 90 bottom
PR164  ev@22_8  [R0805]  159.44 37.61 0 bottom
PR165  4.02k/f_4  [R0402]  157.61 186.96 90 top
PR166  4.02k/f_4  [R0402]  158.6 186.94 90 top
PR167  *short_4  [S0402]  156.39 186.95 90 top
PR168  866k/f_4  [R0402]  155.4 186.94 90 top
PR169  0.01/f_0612  [RC3216]  168.31 174.21 90 bottom
PR170  *short_4  [S0402]  154.41 186.94 90 top
PR171  *short_4  [S0402]  151.54 186.94 90 top
PR172  *short_4  [S0402]  151.47 185.19 180 top
PR173  *short_6  [S0603]  161.77 181.83 0 top
PR174  *100k_4  [R0402]  151.47 184.22 0 top
PR175  *short_4  [S0402]  166 176.7 180 bottom
PR176  *short_4  [S0402]  166 177.67 180 bottom
PR177  *short_4  [S0402]  151.48 183.28 180 top
PR178  *short_4  [S0402]  151.48 182.32 180 top
PR179  *10k_4  [R0402]  151.47 180.31 0 top
PR180  *10_4  [R0402]  138.54 166.52 180 top
PR181  *short_4  [S0402]  135.06 166.36 180 top
PR182  gt3@10/f_6  [R0603]  141.05 169.95 180 bottom
PR183  *short_6  [S0603]  157.99 176.85 90 top
PR184  *short_6  [S0603]  156.6 176.85 90 top
PR185  *short_6  [S0603]  157.38 168.8 270 top
PR186  10/f_6  [R0603]  155.23 176.19 270 top
PR187  *10_4  [R0402]  134.98 168.35 0 top
PR188  gt3@100k/f_4  [R0402]  143.19 170.99 270 bottom
PR189  gt3@100k/f_6  [R0603]  143.57 168.73 90 bottom
PR190  gt3@3.65k/f_6  [R0603]  141.08 168.22 180 bottom
PR191  *short_4  [S0402]  135.03 167.33 180 top
PR192  sp@267/f_4  [R0402]  141.46 171.24 180 bottom
PR193  2.61k/f_4  [R0402]  139.02 170.99 90 bottom
PR194  sp@1.91k/f_4  [R0402]  137.8 170.96 90 bottom
PR195  3k/f_4  [R0402]  136.84 171.04 90 bottom
PR196  *10k/f_4  [R0402]  133.53 172.1 0 bottom
PR197  10k/f_4  [R0402]  133.53 173.12 0 bottom
PR198  sp@88.7k/f_4  [R0402]  137.5 174.64 270 bottom
PR199  4.87k/f_4  [R0402]  144.74 175.94 180 top
PR200  *10k/f_4  [R0402]  133.53 174.01 0 bottom
PR201  1.5k/f_4  [R0402]  146.21 177.11 270 top
PR202  97.6k/f_4  [R0402]  141.19 176.18 0 bottom
PR203  sp@78.7k/f_4  [R0402]  137.23 178.19 180 bottom
PR204  1/f_6  [R0603]  133.51 176.96 180 top
PR205  2.61k/f_4  [R0402]  147.53 181.1 270 top
PR206  63.4k/f_4  [R0402]  135.57 179.72 0 top
PR207  sp@162k_4  [R0402]  139.5 179.12 90 bottom
PR208  11k/f_4  [R0402]  148.16 185.08 90 top
PR209  *short_4  [S0402]  207.9 184.12 0 bottom
PR210  *short_4  [S0402]  207.89 185.16 0 bottom
PR211  267/f_4  [R0402]  145.93 183.48 180 top
PR212  *short_8  [S0805]  133.51 177.29 0 bottom
PR213  0.01/f_0612  [RC3216]  210.8 184.55 180 bottom
PR214  10/f_6  [R0603]  147.66 179.27 180 top
PR215  3.65k/f_6  [R0603]  148.75 181.53 90 top
PR216  2.49k/f_4  [R0402]  142.42 182.82 270 top
PR217  2.05k/f_4  [R0402]  141.36 182.82 270 bottom
PR218  2.61k/f_4  [R0402]  139.35 183.41 180 top
PR219  11k/f_4  [R0402]  139.35 182.44 180 bottom
PR220  475/f_4  [R0402]  137.8 183.13 270 top
PR221  10/f_6  [R0603]  138.74 187.42 180 bottom
PR222  3.65k/f_6  [R0603]  139.71 185.49 270 bottom
PR223  *short_6  [S0603]  121.38 163.81 90 bottom
PR224  13.7k/f_4  [R0402]  136.89 164.38 270 bottom
PR225  13.7k/f_4  [R0402]  126.02 161.84 0 bottom
PR226  27.4k/f_4  [R0402]  125.46 163.24 90 bottom
PR227  470k_4_4700ntc  [R0402]  126.45 163.24 90 bottom
PR228  *short_4  [S0402]  119.3 163.35 90 bottom
PR229  *short_4  [S0402]  120.24 163.38 90 bottom
PR230  *short_6  [S0603]  129.6 163.67 90 bottom
PR231  *short_6  [S0603]  140.98 163.47 90 bottom
PR232  *short_6  [S0603]  152.03 163.52 90 bottom
PR233  gt3@0_4  [R0402]  127.43 163.23 90 bottom
PR234  gt3@0_4  [R0402]  128.44 163.23 90 bottom
PR235  27.4k/f_4  [R0402]  137.27 163.01 0 bottom
PR236  470k_4_4700ntc  [R0402]  137.24 162.05 0 bottom
PR237  *short_4  [S0402]  138.77 163.04 90 bottom
PR238  *short_4  [S0402]  139.74 163.05 90 bottom
PR239  *short_4  [S0402]  149.69 163.11 90 bottom
PR240  *short_4  [S0402]  150.76 163.11 90 bottom
PR241  10k/f_4_3435ntc  [R0402]  115.3 151.68 90 bottom
PR242  10k/f_4_3435ntc  [R0402]  147.48 152.98 90 bottom
PR243  10k/f_4_3435ntc  [R0402]  134.45 152.24 270 bottom
PR250  232k/f_4  [R0402]  48.48 57.02 90 top
PR251  2.2_6  [R0603]  46.05 60.69 0 top
PR252  *short_4  [S0402]  190.68 62.81 0 bottom
PR254  *short_4  [S0402]  66.84 58.51 180 top
PR255  *short_4  [S0402]  204.15 59.58 0 bottom
PR256  *short_4  [S0402]  204.17 58.54 0 bottom
PR257  *short_4  [S0402]  41.43 53.23 90 top
PR258  7.87k/f_4  [R0402]  40.93 55.19 270 top
PR259  ev@10k_4  [R0402]  190.68 61.74 0 bottom
PR260  *ev@1/f_4  [R0402]  197.67 54.12 270 bottom
PR261  499k/f_4  [R0402]  45.25 53.19 90 top
PR262  10k/f_4_3435ntc  [R0402]  35.31 115.92 90 bottom
PR263  *short_4  [S0402]  44.31 53.2 90 top
PR264  *short_4  [S0402]  49.04 54.64 180 top
PR265  *0_4  [R0402]  47.58 54.71 90 top
PR266  10k/f_4  [R0402]  39.58 54.54 0 top
PR267  *short_4  [S0402]  46.23 53.18 90 top
PR268  ev@10k/f_4  [R0402]  197.14 55.98 90 bottom
PR269  100/f_4  [R0402]  40.07 56.55 0 top
PR270  ev@5.36k/f_4  [R0402]  199.17 55.98 90 bottom
PR271  10k_4  [R0402]  168.79 44.67 0 bottom
PR273  *short_4  [S0402]  171.15 47.82 90 bottom
PR274  *short_4  [S0402]  49.05 55.62 0 top
PR275  *ev@499k/f_4  [R0402]  198.08 55.98 270 bottom
PR276  ev@100k/f_4  [R0402]  206.23 62.17 0 bottom
PR277  *short_4  [S0402]  194.42 57.73 180 bottom
PR278  47.5k/f_4  [R0402]  170.74 49.37 0 bottom
PR279  *short_4  [S0402]  194.42 55.82 180 bottom
PR280  *short_4  [S0402]  48.32 84.47 180 top
PR281  *short_4  [S0402]  40.2 58.49 0 top
PR285  *short_6  [S0603]  167.06 51.66 270 bottom
PR286  *short_4  [S0402]  50.3 81.53 0 bottom
PR287  *short_4  [S0402]  50.32 82.57 0 bottom
PR288  *short_4  [S0402]  50.32 84.53 180 bottom
PR289  gt3@100k/f_4  [R0402]  50.3 85.49 180 bottom
PR290  *short_4  [S0402]  57.69 81.17 0 bottom
PR291  *short_6  [S0603]  56.5 84.58 0 bottom
PR292  *short_4  [S0402]  58.15 82.9 90 bottom
PR293  gt3@100k/f_4  [R0402]  57.71 81.17 0 top
PR294  *short_6  [S0603]  54.9 81.15 180 top
PR295  100k/f_4  [R0402]  67.87 70.85 270 bottom
PR296  ev@100k/f_4  [R0402]  216.24 177.73 90 bottom
PR302  15k/f_4  [R0402]  170.31 50.77 90 bottom
PR304  *0_4  [R0402]  46.8 62.01 0 top
PR306  *short_4  [S0402]  168.15 51.68 90 bottom
PR307  *short_4  [S0402]  167.04 44.52 180 bottom
PR309  ev@10k/f_4  [R0402]  204.68 176.52 0 bottom
PR310  ev@7.5k/f_4  [R0402]  204.65 175.53 180 bottom
PR311  *short_4  [S0402]  203.16 174.19 90 bottom
PR312  ev@10_6  [R0603]  207.55 178.33 0 bottom
PR314  100k/f_4  [R0402]  169.32 51.68 90 bottom
PR317  *short_4  [S0402]  204.63 172.41 180 top
PR318  *ev@100k/f_4  [R0402]  202.85 172.38 0 top
PR319  *ev@2.2_6  [R0603]  210.42 172.1 180 bottom
PR321  *short_4  [S0402]  204.63 172.41 0 bottom
PR340  100/f_4  [R0402]  130.49 177.46 90 top
PR341  45.3/f_4  [R0402]  131.5 174.8 180 top
PR342  sp@12.7k/f_4  [R0402]  135.79 170.99 270 top
PR344  gt3@10/f_4  [R0402]  54.08 82.37 180 top
PR345  *short_4  [S0402]  206.23 63.11 0 bottom
PR1247  *short_8  [S0805]  35.11 49.55 0 top
PR1248  *short_8  [S0805]  48.18 48.14 0 top
PR1249  *short_8  [S0805]  158.55 73.43 270 bottom
PR1250  *short_8  [S0805]  160.76 55.57 270 bottom
PR4210  *0_6  [R0603]  76.87 98.62 0 top
PR6120  10k/f_4  [R0402]  55.91 38.37 180 top
PR6121  9.31k/f_4  [R0402]  55.91 39.39 180 top
PR6122  113k/f_4  [R0402]  54.92 40.96 0 top
PR6124  49.9k/f_4  [R0402]  55.94 36.34 180 top
PR6125  *short_6  [S0603]  56.14 37.46 270 bottom
PR6130  *short_6  [S0603]  48.82 41.29 90 top
PR6278  *short_4  [S0402]  53.22 35.15 90 top
PR6279  6.49k/f_4  [R0402]  55.89 40.81 0 bottom
PR6280  10k/f_4  [R0402]  55.89 42.13 0 bottom
PR6281  15.8k/f_4  [R0402]  55.94 37.36 180 top
PR6282  *short_4  [S0402]  66.86 20.62 0 bottom
PR6283  *short_4  [S0402]  54.9 42.97 180 top
PR6284  10k/f_4  [R0402]  53.42 43.43 90 top
PR6285  *short_4  [S0402]  66.73 22.55 0 bottom
PR6286  1/f_6  [R0603]  50.86 42.18 0 top
PR6287  1/f_6  [R0603]  50.53 35.1 180 top
PR6288  *4.7_6  [R0603]  64.78 27.07 90 bottom
PR6289  *4.7_6  [R0603]  63.51 49.07 0 top
PR6290  *10k/f_4  [R0402]  40 52.26 90 top
PR6291  *short_4  [S0402]  66.86 19.65 180 bottom
PR6292  *short_4  [S0402]  59.54 54.55 180 top
PR6293  *short_4  [S0402]  61.8 55.57 0 top
PR6294  *short_4  [S0402]  61.7 53.49 180 top
PR6295  *0_6  [R0603]  75.37 50.95 90 bottom
PR6296  *short_6  [S0603]  59.72 38.2 180 bottom
PR6297  100k_4  [R0402]  54.9 41.98 180 top
PR6298  *22_8  [R0805]  157.54 55.01 180 bottom
PR6299  *short_4  [S0402]  37.88 91.46 270 top
PR6300  *short_4  [S0402]  39.07 91.49 270 top
PR6301  sp@0_4  [R0402]  145.25 171.11 90 top
PR6302  *0_4  [R0402]  45 62.26 180 top
PR6303  *0_4  [R0402]  42.18 54.73 0 top
PR6304  *short_37  [SHORT3720]  133.79 161.82 180 bottom
PR6306  *short_8  [S0805]  71.81 99.97 180 bottom
PR6307  *short_8  [S0805]  69.02 97.3 180 bottom
PU1  isl95859hrtz-t  [QFN40-5X5-4-41P-ISL62771-SMT]  139.2 176.92 0 top
PU2  yb1282psp8  [SOP8-6-1_27-9P]  42.04 48.44 90 top
PU4  as393mtr-e1  [SOIC8-6-1_27]  52.05 111.91 0 top
PU5  bq24780sruyr  [QFN28-4X4-4-38P]  156.72 181.71 180 top
PU6  yb1282psp8  [SOP8-6-1_27-9P]  159.19 67.38 180 bottom
PU7  gt3@aoz5049qi  [POWER-3_5X5-5-14P]  129.58 158.73 0 bottom
PU8  aoz5049qi  [POWER-3_5X5-5-14P]  139.47 158.53 0 bottom
PU9  aoz5029qi-5  [POWER-3_5X5-5-14P]  151.52 158.74 0 bottom
PU10  apl3523a  [SON14-3X2-4-15P-SMT]  58.78 54.45 270 bottom
PU11  apl3523a  [SON14-3X2-4-15P-SMT]  63.66 20.82 270 bottom
PU13  aoz5049qi  [POWER-3_5X5-5-14P]  119.89 158.77 0 bottom
PU14  gt3@nb681gd-z  [QFN13-2X3-5]  53.85 82.62 180 bottom
PU15  g5335qt2u  [QFN23-4X4-5-25P]  64.77 75.11 180 bottom
PU16  g5719ctb1u  [TSOP6-2_8-95]  168.05 47.97 270 bottom
PU18  ev@rt8068azqw  [DFN10-3X3-5-11P-RT9296]  207.4 175.05 180 bottom
PU19  ev@up1658rqkf  [QFN20-3X3-4-21P-0_8H]  199.85 60.14 270 bottom
PU20  typec@apl3523a  [SON14-3X2-4-15P-SMT]  38.36 96.92 0 top
PU21  rt8231bgqw  [WQFN20-3X3-4-21P]  44.74 56.76 270 top
PU22  ev@g5335qt2u  [QFN23-4X4-5-25P]  220.19 174.04 0 bottom
PU6010  tps51225rukr  [QFN20-3X3-4-26P]  52.41 38.73 90 top
Q1  *tsi@2n7002k  [SOT23_213-3_3-2]  132.49 179.47 90 top
Q2  *tsi@2n7002dw  [SC70-2_1-65-6P]  119.44 175.41 180 top
Q3  2n7002dw  [SC70-2_1-65-6P]  114.36 154.58 270 top
Q4  dtc144eua  [UMT_213-3-1_3]  110.93 158.52 180 top
Q5  mmbt3904-7-f  [SOT23_213-3_3-2]  100.77 135.5 0 bottom
Q15  typec@2n7002k  [SOT23_213-3_3-2]  26.22 104.92 0 top
Q17  typec@2n7002k  [SOT23_213-3_3-2]  23.04 107.46 0 top
Q18  bl@ao3413  [SOT23_213-3_3-2]  225.61 144.04 90 bottom
Q19  bl@dtc144eu  [UMT_213-3-1_3]  224.47 126.89 180 bottom
Q20  *tdi@2n7002k  [SOT23_213-3_3-2]  154.18 113.51 0 bottom
Q21  ap2331sa-7  [SOT23_213-3_3-2]  13.34 84.93 270 bottom
Q22  *ioac@ao3413  [SOT23_213-3_3-2]  205.29 190.77 90 bottom
Q23  2n7002dw  [SC70-2_1-65-6P]  178.62 177.57 270 bottom
Q24  *ioac@ao3413  [SOT23_213-3_3-2]  48.11 67.58 0 top
Q25  2n7002k  [SOT23_213-3_3-2]  33.33 61.23 0 top
Q26  ap2331sa-7  [SOT23_213-3_3-2]  18.6 58.06 180 top
Q27  *dtc144eu  [UMT_213-3-1_3]  207.83 42.67 270 bottom
Q28  *ao3404  [SOT23_213-3_3-2]  211.21 44.34 90 bottom
Q29  *pja138k  [SOT23_213-3_3-2]  201.28 44.8 0 bottom
Q30  2n7002k  [SOT23_213-3_3-2]  192.59 32.02 90 bottom
Q31  fdv301n  [SOT23_213-3_3-2]  96.17 135.5 90 bottom
Q32  2n7002dw  [SC70-2_1-65-6P]  155.38 118.13 0 top
Q34  *ioac@ao6402a  [TSOP6-2_8-95]  222.41 101.44 180 bottom
Q35  *dtc144eu  [UMT_213-3-1_3]  91.75 102.38 0 bottom
Q36  *ioac@dmn601k-7  [SOT23_213-3_3-2]  224.95 108.1 0 bottom
Q37  *ioac@2n7002dw  [SC70-2_1-65-6P]  225.2 111.32 0 bottom
Q38  *ioac@ao3413  [SOT23_213-3_3-2]  205.29 186.96 270 bottom
Q39  *ioac@2n7002k  [SOT23_213-3_3-2]  45.65 80.28 180 top
Q40  pja138k  [SOT23_213-3_3-2]  218.12 67.84 90 bottom
Q41  *2n7002k  [SOT23_213-3_3-2]  25.71 56.79 270 top
Q42  *ao3413  [SOT23_213-3_3-2]  132.99 13.99 90 bottom
Q43  *2n7002dw  [SC70-2_1-65-6P]  137.72 14.88 180 bottom
Q56  *pj4n3kdw  [SC70-2_1-65-6P]  218.75 71.77 90 bottom
Q59  2n7002k  [SOT23_213-3_3-2]  169.73 109.11 270 bottom
Q75  fpd@ao3413  [SOT23_213-3_3-2]  112.58 32.91 0 top
Q76  *fpd@dtc144eua  [UMT_213-3-1_3]  116.95 32.46 90 top
Q115  ev_b@2n7002d  [SOT23_213-3_3-2]  209.23 154.83 180 bottom
Q129  ev_a@2n7002d  [SOT23_213-3_3-2]  207.32 158.77 270 bottom
Q4000  gc6@ao3413  [SOT23_213-3_3-2]  170.36 109.85 180 top
Q4001  gc6@2n7002k  [SOT23_213-3_3-2]  166.44 108.82 270 top
Q4002  ev@2n7002kw_115ma  [UMT_213-3-1_3]  171.35 113.46 90 bottom
Q4200  ev@dtc144eu  [UMT_213-3-1_3]  178.24 107.84 270 bottom
Q4201  ev@mmbt3904-7-f  [SOT23_213-3_3-2]  173.46 107.84 90 bottom
Q4202  ev@dtc144eua  [UMT_213-3-1_3]  160.08 139.59 90 bottom
Q4203  ev@metr3904-g  [SOT23_213-3_3-2]  163.63 139.74 90 bottom
Q4300  *ev@me2n7002dkw-g_115ma  [SC70-2_1-65-6P]  192.11 106.93 180 bottom
